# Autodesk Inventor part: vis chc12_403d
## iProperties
Author: ajt
Created: 2001-10
Part Number: vis chc12_403d
Material: Par défaut
Document SubType Name: Proxy Part
Designer: ajt
Control State: 0
Master: False
Checked Out: False
PropertySet Name: Design Tracking Control
Shininess: 21.0
PropertySet Name: _Private Model Information
Length Units: 11269
Angle Units: 11283
Time Units: 11279
Mass Units: 11290
Length Display Precision: 3
Angle Display Precision: 2
Compacted: False
Density: 0.0
Volumn: 0.0
Area: 0.0
PropertySet Name: Model Information
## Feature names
1. LinkedPart1
